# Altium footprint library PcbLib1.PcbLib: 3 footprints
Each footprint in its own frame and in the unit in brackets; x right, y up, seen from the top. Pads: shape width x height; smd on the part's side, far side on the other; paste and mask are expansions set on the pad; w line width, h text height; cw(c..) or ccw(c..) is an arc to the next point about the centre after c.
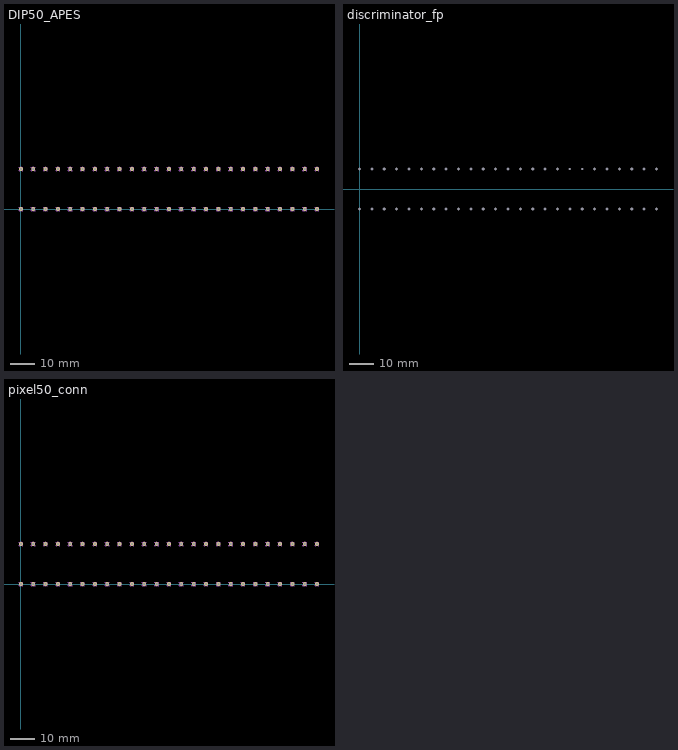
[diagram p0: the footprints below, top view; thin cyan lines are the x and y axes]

## DIP50_APES [mil]
pads (50):
  oct 61x61 hole 36: 1(0,0) 1(0,650) 1(200,0) 1(200,650) 1(400,0) 1(400,650) 1(600,0) 1(600,650) 1(800,0) 1(800,650) 1(1000,0) 1(1000,650) 1(1200,0) 1(1200,650) 1(1400,0) 1(1400,650) 1(1600,0) 1(1600,650) 1(1800,0) 1(1800,650) 1(2000,0) 1(2000,650) 1(2200,0) 1(2200,650) 1(2400,0) 1(2400,650) 1(2600,0) 1(2600,650) 1(2800,0) 1(2800,650) 1(3000,0) 1(3000,650) 1(3200,0) 1(3200,650) 1(3400,0) 1(3400,650) 1(3600,0) 1(3600,650) 1(3800,0) 1(3800,650) 1(4000,0) 1(4000,650) 1(4200,0) 1(4200,650) 1(4400,0) 1(4400,650) 1(4600,0) 1(4600,650) 1(4800,0) 1(4800,650)
Mechanical 2:
  drawing of 400 lines, arcs and shapes, not listed
Mechanical 8:
  circle w6: c0,650 r25
  circle w6: c0,0 r25
  circle w6: c200,650 r25
  circle w6: c200,0 r25
  circle w6: c400,650 r25
  circle w6: c400,0 r25
  circle w6: c600,650 r25
  circle w6: c600,0 r25
  circle w6: c800,650 r25
  circle w6: c800,0 r25
  circle w6: c1000,650 r25
  circle w6: c1000,0 r25
  circle w6: c1200,650 r25
  circle w6: c1200,0 r25
  circle w6: c1400,650 r25
  circle w6: c1400,0 r25
  circle w6: c1600,650 r25
  circle w6: c1600,0 r25
  circle w6: c1800,650 r25
  circle w6: c1800,0 r25
  circle w6: c2000,650 r25
  circle w6: c2000,0 r25
  circle w6: c2200,650 r25
  circle w6: c2200,0 r25
  circle w6: c2400,650 r25
  circle w6: c2400,0 r25
  circle w6: c2600,650 r25
  circle w6: c2600,0 r25
  circle w6: c2800,650 r25
  circle w6: c2800,0 r25
  circle w6: c3000,650 r25
  circle w6: c3000,0 r25
  circle w6: c3200,650 r25
  circle w6: c3200,0 r25
  circle w6: c3400,650 r25
  circle w6: c3400,0 r25
  circle w6: c3600,650 r25
  circle w6: c3600,0 r25
  circle w6: c3800,650 r25
  circle w6: c3800,0 r25
  circle w6: c4000,650 r25
  circle w6: c4000,0 r25
  circle w6: c4200,650 r25
  circle w6: c4200,0 r25
  circle w6: c4400,650 r25
  circle w6: c4400,0 r25
  circle w6: c4600,650 r25
  circle w6: c4600,0 r25
  circle w6: c4800,650 r25
  circle w6: c4800,0 r25

## discriminator_fp [mil]
pads (50):
  round 0 hole 50: 1(0,325) 2(0,-325) 3(200,325) 4(200,-325) 5(400,325) 6(400,-325) 7(600,325) 8(600,-325) 9(800,325) 10(800,-325) 11(1000,325) 12(1000,-325) 13(1200,325) 14(1200,-325) 15(1400,325) 16(1400,-325) 17(1600,325) 18(1600,-325) 19(1800,325) 20(1800,-325) 21(2000,325) 22(2000,-325) 23(2200,325) 24(2200,-325) 25(2400,325) 26(2400,-325) 27(2600,325) 28(2600,-325) 29(2800,325) 30(2800,-325) 31(3000,325) 32(3000,-325) 33(3200,325) 34(3200,-325) 36(3400,-325) 38(3600,-325) 39(3800,325) 40(3800,-325) 41(4000,325) 42(4000,-325) 43(4200,325) 44(4200,-325) 45(4400,325) 46(4400,-325) 47(4600,325) 48(4600,-325) 49(4800,325) 50(4800,-325)
  oct 0x0 hole 36: 35(3400,325) 37(3600,325)
Top Layer:
  text "Pixel5" at 360,305 h35
  text "Pixel3" at 165,305 h35
  text "Pixel1" at -45,310 h35
  text "Pixel7" at 560,305 h35
  text "Pixel9" at 760,305 h35
  text "Pixel11" at 960,305 h35
  text "Pixel13" at 1160,305 h35
  text "Pixel15" at 1355,305 h35
  text "Pixel17" at 1560,305 h35
  text "Pixel19" at 1755,305 h35
  text "Pixel21" at 1960,305 h35
  text "Pixel23" at 2165,305 h35
  text "Pixel25" at 2365,305 h35
  text "Pixel27" at 2560,305 h35
  text "Pixel29" at 2760,305 h35
  text "Pixel31" at 2960,305 h35
  text "Pixel33" at 3155,305 h35
  text "Pixel35" at 3360,305 h35
  text "Pixel37" at 3550,305 h35
  text "Pixel39" at 3760,305 h35
  text "Pixel41" at 3950,305 h35
  text "Pixel43" at 4160,305 h35
  text "Pixel45" at 4360,305 h35
  text "Pixel47" at 4565,305 h35
  text "Pixel49" at 4760,305 h35
  text "Pixel30" at 2755,-345 h35
  text "Pixel32" at 2950,-350 h35
  text "Pixel34" at 3155,-345 h35
  text "Pixel36" at 3350,-345 h35
  text "Pixel38" at 3555,-345 h35
  text "Pixel40" at 3755,-345 h35
  text "Pixel42" at 3955,-345 h35
  text "Pixel44" at 4160,-345 h35
  text "Pixel46" at 4360,-345 h35
  text "Pixel48" at 4565,-345 h35
  text "Pixel50" at 4765,-345 h35
  text "Pixel28" at 2565,-345 h35
  text "Pixel26" at 2365,-345 h35
  text "Pixel24" at 2160,-345 h35
  text "Pixel22" at 1960,-345 h35
  text "Pixel20" at 1765,-345 h35
  text "Pixel18" at 1560,-345 h35
  text "Pixel16" at 1365,-345 h35
  text "Pixel14" at 1165,-345 h35
  text "Pixel12" at 960,-345 h35
  text "Pixel10" at 760,-345 h35
  text "Pixel8" at 560,-345 h35
  text "Pixel6" at 365,-345 h35
  text "Pixel6" at 165,-345 h35
  text "Pixel6" at -35,-345 h35

## pixel50_conn [mil] "Pixel Connector 50"
pads (50):
  oct 61x61 hole 36: 1(0,650) 2(0,0) 3(200,650) 4(200,0) 5(400,650) 6(400,0) 7(600,650) 8(600,0) 9(800,650) 10(800,0) 11(1000,650) 12(1000,0) 13(1200,650) 14(1200,0) 15(1400,650) 16(1400,0) 17(1600,650) 18(1600,0) 19(1800,650) 20(1800,0) 21(2000,650) 22(2000,0) 23(2200,650) 24(2200,0) 25(2400,650) 26(2400,0) 27(2600,650) 28(2600,0) 29(2800,650) 30(2800,0) 31(3000,650) 32(3000,0) 33(3200,650) 34(3200,0) 35(3400,650) 36(3400,0) 37(3600,650) 38(3600,0) 39(3800,650) 40(3800,0) 41(4000,650) 42(4000,0) 43(4200,650) 44(4200,0) 45(4400,650) 46(4400,0) 47(4600,650) 48(4600,0) 49(4800,650) 50(4800,0)
Top Layer:
  text "Pixel50" at 4835,-405 h50
  text "Pixel40" at 3835,-405 h50
  text "Pixel38" at 3635,-405 h50
  text "Pixel36" at 3435,-405 h50
  text "Pixel34" at 3235,-405 h50
  text "Pixel46" at 4435,-410 h50
  text "Pixel48" at 4635,-410 h50
  text "Pixel42" at 4035,-405 h50
  text "Pixel44" at 4230,-410 h50
  text "Pixel33" at 3235,720 h50
  text "Pixel35" at 3435,720 h50
  text "Pixel37" at 3635,720 h50
  text "Pixel39" at 3835,720 h50
  text "Pixel31" at 3030,720 h50
  text "Pixel41" at 4030,720 h50
  text "Pixel49" at 4835,720 h50
  text "Pixel47" at 4635,725 h50
  text "Pixel45" at 4435,720 h50
  text "Pixel43" at 4235,720 h50
  text "Pixel24" at 2230,-410 h50
  text "Pixel22" at 2035,-405 h50
  text "Pixel32" at 3035,-405 h50
  text "Pixel30" at 2835,-405 h50
  text "Pixel28" at 2635,-405 h50
  text "Pixel26" at 2435,-410 h50
  text "Pixel3" at 245,720 h50
  text "Pixel5" at 445,720 h50
  text "Pixel7" at 645,720 h50
  text "Pixel9" at 845,720 h50
  text "Pixel1" at 40,720 h50
  text "Pixel23" at 2240,720 h50
  text "Pixel25" at 2440,720 h50
  text "Pixel27" at 2640,725 h50
  text "Pixel29" at 2840,720 h50
  text "Pixel21" at 2035,720 h50
  text "Pixel11" at 1035,720 h50
  text "Pixel19" at 1840,720 h50
  text "Pixel17" at 1640,720 h50
  text "Pixel15" at 1440,720 h50
  text "Pixel13" at 1240,720 h50
  text "Pixel14" at 1235,-405 h50
  text "Pixel16" at 1435,-405 h50
  text "Pixel18" at 1635,-405 h50
  text "Pixel20" at 1835,-405 h50
  text "Pixel10" at 835,-400 h50
  text "Pixel8" at 630,-405 h50
  text "Pixel12" at 1030,-405 h50
  text "Pixel6" at 425,-405 h50
  text "Pixel2" at 30,-400 h50
  text "Pixel4" at 235,-400 h50
Mechanical 2:
  drawing of 400 lines, arcs and shapes, not listed
Mechanical 8:
  circle w6: c0,650 r25
  circle w6: c0,0 r25
  circle w6: c200,650 r25
  circle w6: c200,0 r25
  circle w6: c400,650 r25
  circle w6: c400,0 r25
  circle w6: c600,650 r25
  circle w6: c600,0 r25
  circle w6: c800,650 r25
  circle w6: c800,0 r25
  circle w6: c1000,650 r25
  circle w6: c1000,0 r25
  circle w6: c1200,650 r25
  circle w6: c1200,0 r25
  circle w6: c1400,650 r25
  circle w6: c1400,0 r25
  circle w6: c1600,650 r25
  circle w6: c1600,0 r25
  circle w6: c1800,650 r25
  circle w6: c1800,0 r25
  circle w6: c2000,650 r25
  circle w6: c2000,0 r25
  circle w6: c2200,650 r25
  circle w6: c2200,0 r25
  circle w6: c2400,650 r25
  circle w6: c2400,0 r25
  circle w6: c2600,650 r25
  circle w6: c2600,0 r25
  circle w6: c2800,650 r25
  circle w6: c2800,0 r25
  circle w6: c3000,650 r25
  circle w6: c3000,0 r25
  circle w6: c3200,650 r25
  circle w6: c3200,0 r25
  circle w6: c3400,650 r25
  circle w6: c3400,0 r25
  circle w6: c3600,650 r25
  circle w6: c3600,0 r25
  circle w6: c3800,650 r25
  circle w6: c3800,0 r25
  circle w6: c4000,650 r25
  circle w6: c4000,0 r25
  circle w6: c4200,650 r25
  circle w6: c4200,0 r25
  circle w6: c4400,650 r25
  circle w6: c4400,0 r25
  circle w6: c4600,650 r25
  circle w6: c4600,0 r25
  circle w6: c4800,650 r25
  circle w6: c4800,0 r25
